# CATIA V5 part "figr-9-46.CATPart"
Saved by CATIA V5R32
Part number: Part1
Bounding box of the stored display mesh (mm): x -159.661 to 182.627, y -78.048 to 78.048, z 0 to 72.429
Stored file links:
  D:\PROJECTS\Project 2022\CATIA V5 6R 2022\Resources\Part Files\c09_catia_v5_6r2022_prt\c09_catia_v5_6r2022_prt\figr-9-46.CATPart
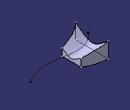
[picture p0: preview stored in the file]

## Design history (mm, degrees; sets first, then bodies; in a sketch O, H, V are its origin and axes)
Body1 (main body)
  Plane1: type Offset, RefPlane yz-plane, Offset 100
  Plane2: type Offset, RefPlane yz-plane, Offset 100, reversed
  Sketch1 on Plane1, origin (100, 0, 0), H (0, 1, 0), V (0, 0, 1)
    point P1 (0, 15.965)
    hyperbola C1
    point P2 (0, 3.0416)
    line L1 (54.8261, 44.8858) -> (54.8261, 0)
    point P5 (54.8261, 0)
    line L2 (-54.8261, 44.8858) -> (-54.8261, 0)
    point P6 (-54.8261, 0)
    line L3 (-54.8261, 0) -> (54.8261, 0)
    coincidence: P1 V, P2 V, P5 H, P6 H
    vertical: L1 V, L2 V
    horizontal: L3 H
  Sketch2 on xy-plane, origin (0, 0, 0), H (1, 0, 0), V (0, 1, 0)
    spline S1 through (-159.6608, -77.1468) (-77.8466, -31.8169) (23.6283, -41.4968) (182.6271, -11.7333)
  Sketch3 on yz-plane, origin (0, 0, 0), H (0, 1, 0), V (0, 0, 1)
    point P1 (0, 18.9787)
    hyperbola C1
    point P2 (0, 2.6681)
    line L1 (48.2237, 37.1764) -> (48.2237, 0)
    point P5 (48.2237, 0)
    line L2 (-43.6563, 34.1546) -> (-43.6563, 0)
    point P6 (-43.6563, 0)
    line L3 (-43.6563, 0) -> (48.2237, 0)
    coincidence: P1 V, P2 V, P5 H, P6 H
    vertical: L1 V, L2 V
    horizontal: L3 H
  Sketch4 on Plane2, origin (-100, 0, 0), H (0, 1, 0), V (0, 0, 1)
    point P1 (0, 140.6052)
    point P2 (0, 41.8972)
    hyperbola C1
    line L1 (78.0478, 72.4293) -> (78.0478, 0)
    point P5 (78.0478, 0)
    line L2 (-78.0478, 72.4293) -> (-78.0478, 0)
    point P6 (-78.0478, 0)
    line L3 (-78.0478, 0) -> (78.0478, 0)
    coincidence: P1 V, P2 V, P5 H, P6 H
    vertical: L1 V, L2 V
    horizontal: L3 H
  Loft1: solid, Sections (Sketch3; Sketch4), Spine Sketch2
  Loft2: solid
